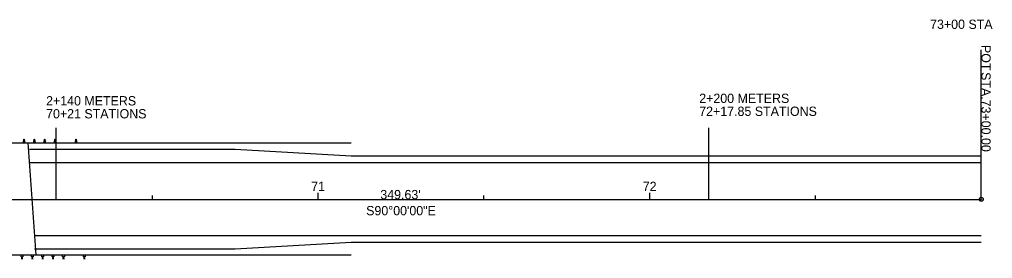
# Model space of a CAD drawing. Extents: x 27625 to 127752, y 6088 to 302357.
# Drawn here: x 27917.3 to 28210.8, y 6088.8 to 6160.8 of the extents above; entities that cross this region are included whole.
import ezdxf

# ---------------------------------------------------------------- set-up
doc = ezdxf.new("R2010")
doc.units = 0
for name, color, linetype in [('DR_X_Cells', 7, 'Continuous'), ('RS_Raster1', 7, 'Continuous'), ('RW_X_CL_100_Bearings', 7, 'Continuous'), ('RW_X_CL_100_Cardinal_Points', 7, 'Continuous'), ('RW_X_CL_100_Curve_Data', 7, 'Continuous'), ('RW_X_CL_100_Distances', 7, 'Continuous'), ('RW_X_CL_100_Stations', 7, 'Continuous'), ('SC_Scratch1', 7, 'Continuous'), ('SC_Scratch2', 7, 'Continuous'), ('SC_Scratch4', 7, 'Continuous'), ('SV_P_Control_Cells_Set', 7, 'Continuous'), ('SV_X_Mon_Cells_Found', 7, 'Continuous'), ('SV_X_Random_Point', 7, 'Continuous'), ('SV_X_Shot_Marker', 7, 'Continuous'), ('UT_X_Telecom_Cells', 7, 'Continuous')]:
    doc.layers.add(name, color=color, linetype=linetype)

msp = doc.modelspace()

# ---------------------------------------------------------------- linework, layer by layer
at = {"layer": 'DR_X_Cells'}
for p, q in [((27957.41, 6106.66), (27957.41, 6107.86)), ((28007.41, 6106.66), (28007.41, 6108.66)), ((28057.41, 6106.66), (28057.41, 6107.86)), ((28107.41, 6106.66), (28107.41, 6108.66)), ((28157.41, 6106.66), (28157.41, 6107.86))]:
    msp.add_line(p, q, dxfattribs=at)
at = {"layer": 'RS_Raster1'}
for centre in [(28007.41, 6106.66), (28107.41, 6106.66), (28207.41, 6106.66)]:
    msp.add_circle(centre, 0.05, dxfattribs=at)
at = {"layer": 'RW_X_CL_100_Bearings'}
for p, q in [((27904.89, 6123.66), (27919.89, 6123.66)), ((27919.89, 6123.66), (27922.25, 6089.91)), ((27907.25, 6089.91), (27922.25, 6089.91))]:
    msp.add_line(p, q, dxfattribs=at)
at = {"layer": 'RW_X_CL_100_Cardinal_Points'}
for p, q in [((27919.73, 6123.66), (27934.33, 6123.66)), ((27934.33, 6123.66), (27934.33, 6123.66)), ((27922.25, 6089.91), (27936.85, 6089.91)), ((27936.85, 6089.91), (27936.85, 6089.91))]:
    msp.add_line(p, q, dxfattribs=at)
at = {"layer": 'RW_X_CL_100_Curve_Data'}
for p, q in [((27918.45, 6124.72), (27918.96, 6124.72)), ((27918.45, 6124.72), (27918.45, 6124.68)), ((27918.45, 6124.68), (27918.66, 6124.68)), ((27918.45, 6124.23), (27918.45, 6124.19)), ((27918.45, 6124.23), (27918.66, 6124.23)), ((27918.45, 6124.19), (27918.96, 6124.19)), ((27918.45, 6124.19), (27918.45, 6123.66)), ((27918.69, 6124.65), (27918.69, 6124.26)), ((27918.72, 6124.65), (27918.72, 6124.26)), ((27918.75, 6124.68), (27918.96, 6124.68)), ((27918.75, 6124.23), (27918.96, 6124.23)), ((27918.96, 6124.72), (27918.96, 6124.68)), ((27918.96, 6124.23), (27918.96, 6124.19)), ((27918.96, 6123.66), (27918.96, 6124.19)), ((27921.58, 6124.72), (27922.09, 6124.72)), ((27921.58, 6124.72), (27921.58, 6124.68)), ((27921.58, 6124.68), (27921.78, 6124.68)), ((27921.58, 6124.23), (27921.58, 6124.19)), ((27921.58, 6124.23), (27921.78, 6124.23)), ((27921.58, 6124.19), (27922.09, 6124.19)), ((27921.58, 6124.19), (27921.58, 6123.66)), ((27921.81, 6124.65), (27921.81, 6124.26)), ((27921.85, 6124.65), (27921.85, 6124.26)), ((27921.88, 6124.68), (27922.09, 6124.68)), ((27921.88, 6124.23), (27922.09, 6124.23)), ((27922.09, 6124.72), (27922.09, 6124.68)), ((27922.09, 6124.23), (27922.09, 6124.19)), ((27922.09, 6123.66), (27922.09, 6124.19)), ((27924.7, 6124.72), (27925.21, 6124.72)), ((27924.7, 6124.72), (27924.7, 6124.68)), ((27924.7, 6124.68), (27924.91, 6124.68)), ((27924.7, 6124.23), (27924.7, 6124.19)), ((27924.7, 6124.23), (27924.91, 6124.23)), ((27924.7, 6124.19), (27925.21, 6124.19)), ((27924.7, 6124.19), (27924.7, 6123.66)), ((27924.94, 6124.65), (27924.94, 6124.26)), ((27924.97, 6124.65), (27924.97, 6124.26)), ((27925, 6124.68), (27925.21, 6124.68)), ((27925, 6124.23), (27925.21, 6124.23)), ((27925.21, 6124.72), (27925.21, 6124.68)), ((27925.21, 6124.23), (27925.21, 6124.19)), ((27925.21, 6123.66), (27925.21, 6124.19)), ((27927.83, 6124.72), (27928.34, 6124.72)), ((27927.83, 6124.72), (27927.83, 6124.68)), ((27927.83, 6124.68), (27928.03, 6124.68)), ((27927.83, 6124.23), (27927.83, 6124.19)), ((27927.83, 6124.23), (27928.03, 6124.23)), ((27927.83, 6124.19), (27928.34, 6124.19)), ((27927.83, 6124.19), (27927.83, 6123.66)), ((27928.06, 6124.65), (27928.06, 6124.26)), ((27928.1, 6124.65), (27928.1, 6124.26)), ((27928.13, 6124.68), (27928.34, 6124.68)), ((27928.13, 6124.23), (27928.34, 6124.23)), ((27928.34, 6124.72), (27928.34, 6124.68)), ((27928.34, 6124.23), (27928.34, 6124.19)), ((27928.34, 6123.66), (27928.34, 6124.19)), ((27934.08, 6124.72), (27934.59, 6124.72)), ((27934.08, 6124.72), (27934.08, 6124.68)), ((27934.08, 6124.68), (27934.28, 6124.68)), ((27934.08, 6124.23), (27934.08, 6124.19)), ((27934.08, 6124.23), (27934.28, 6124.23)), ((27934.08, 6124.19), (27934.59, 6124.19)), ((27934.08, 6124.19), (27934.08, 6123.66)), ((27934.31, 6124.65), (27934.31, 6124.26)), ((27934.35, 6124.65), (27934.35, 6124.26)), ((27934.38, 6124.68), (27934.59, 6124.68)), ((27934.38, 6124.23), (27934.59, 6124.23)), ((27934.59, 6124.72), (27934.59, 6124.68)), ((27934.59, 6124.23), (27934.59, 6124.19)), ((27934.59, 6123.66), (27934.59, 6124.19)), ((27917.85, 6089.38), (27917.85, 6089.91)), ((27917.85, 6089.38), (27918.36, 6089.38)), ((27917.85, 6089.34), (27917.85, 6089.38)), ((27917.85, 6089.34), (27918.05, 6089.34)), ((27917.85, 6088.85), (27917.85, 6088.88)), ((27917.85, 6088.88), (27918.05, 6088.88)), ((27917.85, 6088.85), (27918.36, 6088.85)), ((27918.08, 6088.91), (27918.08, 6089.31)), ((27918.12, 6088.91), (27918.12, 6089.31)), ((27918.15, 6089.34), (27918.36, 6089.34)), ((27918.15, 6088.88), (27918.36, 6088.88)), ((27918.36, 6089.91), (27918.36, 6089.38)), ((27918.36, 6089.34), (27918.36, 6089.38)), ((27918.36, 6088.85), (27918.36, 6088.88)), ((27920.97, 6089.38), (27920.97, 6089.91)), ((27920.97, 6089.38), (27921.48, 6089.38)), ((27920.97, 6089.34), (27920.97, 6089.38)), ((27920.97, 6089.34), (27921.18, 6089.34)), ((27920.97, 6088.85), (27920.97, 6088.88)), ((27920.97, 6088.88), (27921.18, 6088.88)), ((27920.97, 6088.85), (27921.48, 6088.85)), ((27921.21, 6088.91), (27921.21, 6089.31)), ((27921.24, 6088.91), (27921.24, 6089.31)), ((27921.27, 6089.34), (27921.48, 6089.34)), ((27921.27, 6088.88), (27921.48, 6088.88)), ((27921.48, 6089.91), (27921.48, 6089.38)), ((27921.48, 6089.34), (27921.48, 6089.38)), ((27921.48, 6088.85), (27921.48, 6088.88)), ((27924.1, 6089.38), (27924.1, 6089.91)), ((27924.1, 6089.38), (27924.61, 6089.38)), ((27924.1, 6089.34), (27924.1, 6089.38)), ((27924.1, 6089.34), (27924.3, 6089.34)), ((27924.1, 6088.85), (27924.1, 6088.88)), ((27924.1, 6088.88), (27924.3, 6088.88)), ((27924.1, 6088.85), (27924.61, 6088.85)), ((27924.33, 6088.91), (27924.33, 6089.31)), ((27924.37, 6088.91), (27924.37, 6089.31)), ((27924.4, 6089.34), (27924.61, 6089.34)), ((27924.4, 6088.88), (27924.61, 6088.88)), ((27924.61, 6089.91), (27924.61, 6089.38)), ((27924.61, 6089.34), (27924.61, 6089.38)), ((27924.61, 6088.85), (27924.61, 6088.88)), ((27927.22, 6089.38), (27927.22, 6089.91)), ((27927.22, 6089.38), (27927.73, 6089.38)), ((27927.22, 6089.34), (27927.22, 6089.38)), ((27927.22, 6089.34), (27927.43, 6089.34)), ((27927.22, 6088.85), (27927.22, 6088.88)), ((27927.22, 6088.88), (27927.43, 6088.88)), ((27927.22, 6088.85), (27927.73, 6088.85)), ((27927.46, 6088.91), (27927.46, 6089.31)), ((27927.49, 6088.91), (27927.49, 6089.31)), ((27927.52, 6089.34), (27927.73, 6089.34)), ((27927.52, 6088.88), (27927.73, 6088.88)), ((27927.73, 6089.91), (27927.73, 6089.38)), ((27927.73, 6089.34), (27927.73, 6089.38)), ((27927.73, 6088.85), (27927.73, 6088.88)), ((27930.35, 6089.38), (27930.35, 6089.91)), ((27930.35, 6089.38), (27930.86, 6089.38)), ((27930.35, 6089.34), (27930.35, 6089.38)), ((27930.35, 6089.34), (27930.55, 6089.34)), ((27930.35, 6088.85), (27930.35, 6088.88)), ((27930.35, 6088.88), (27930.55, 6088.88)), ((27930.35, 6088.85), (27930.86, 6088.85)), ((27930.58, 6088.91), (27930.58, 6089.31)), ((27930.62, 6088.91), (27930.62, 6089.31)), ((27930.65, 6089.34), (27930.86, 6089.34)), ((27930.65, 6088.88), (27930.86, 6088.88)), ((27930.86, 6089.91), (27930.86, 6089.38)), ((27930.86, 6089.34), (27930.86, 6089.38)), ((27930.86, 6088.85), (27930.86, 6088.88)), ((27936.6, 6089.38), (27936.6, 6089.91)), ((27936.6, 6089.38), (27937.11, 6089.38)), ((27936.6, 6089.34), (27936.6, 6089.38)), ((27936.6, 6089.34), (27936.8, 6089.34)), ((27936.6, 6088.85), (27936.6, 6088.88)), ((27936.6, 6088.88), (27936.8, 6088.88)), ((27936.6, 6088.85), (27937.11, 6088.85)), ((27936.83, 6088.91), (27936.83, 6089.31)), ((27936.87, 6088.91), (27936.87, 6089.31)), ((27936.9, 6089.34), (27937.11, 6089.34)), ((27936.9, 6088.88), (27937.11, 6088.88)), ((27937.11, 6089.91), (27937.11, 6089.38)), ((27937.11, 6089.34), (27937.11, 6089.38)), ((27937.11, 6088.85), (27937.11, 6088.88))]:
    msp.add_line(p, q, dxfattribs=at)
for centre, start, end in [((27918.66, 6124.65), 0, 90), ((27918.66, 6124.26), 270, 0), ((27918.75, 6124.65), 90, 180), ((27918.75, 6124.26), 180, 270), ((27921.78, 6124.65), 0, 90), ((27921.78, 6124.26), 270, 0), ((27921.88, 6124.65), 90, 180), ((27921.88, 6124.26), 180, 270), ((27924.91, 6124.65), 0, 90), ((27924.91, 6124.26), 270, 0), ((27925, 6124.65), 90, 180), ((27925, 6124.26), 180, 270), ((27928.03, 6124.65), 0, 90), ((27928.03, 6124.26), 270, 0), ((27928.13, 6124.65), 90, 180), ((27928.13, 6124.26), 180, 270), ((27934.28, 6124.65), 0, 90), ((27934.28, 6124.26), 270, 0), ((27934.38, 6124.65), 90, 180), ((27934.38, 6124.26), 180, 270), ((27918.05, 6089.31), 0, 90), ((27918.05, 6088.91), 270, 0), ((27918.15, 6089.31), 90, 180), ((27918.15, 6088.91), 180, 270), ((27921.18, 6089.31), 0, 90), ((27921.18, 6088.91), 270, 0), ((27921.27, 6089.31), 90, 180), ((27921.27, 6088.91), 180, 270), ((27924.3, 6089.31), 0, 90), ((27924.3, 6088.91), 270, 0), ((27924.4, 6089.31), 90, 180), ((27924.4, 6088.91), 180, 270), ((27927.43, 6089.31), 0, 90), ((27927.43, 6088.91), 270, 0), ((27927.52, 6089.31), 90, 180), ((27927.52, 6088.91), 180, 270), ((27930.55, 6089.31), 0, 90), ((27930.55, 6088.91), 270, 0), ((27930.65, 6089.31), 90, 180), ((27930.65, 6088.91), 180, 270), ((27936.8, 6089.31), 0, 90), ((27936.8, 6088.91), 270, 0), ((27936.9, 6089.31), 90, 180), ((27936.9, 6088.91), 180, 270)]:
    msp.add_arc(centre, 0.0312, start, end, dxfattribs=at)
at = {"layer": 'RW_X_CL_100_Distances'}
msp.add_line((27936.85, 6089.91), (28017.41, 6089.91), dxfattribs=at)
at = {"layer": 'RW_X_CL_100_Stations'}
for p, q in [((27918.45, 6123.66), (27918.96, 6123.66)), ((27921.58, 6123.66), (27922.09, 6123.66)), ((27924.7, 6123.66), (27925.21, 6123.66)), ((27927.83, 6123.66), (27928.34, 6123.66)), ((27934.08, 6123.66), (27934.59, 6123.66)), ((27917.85, 6089.91), (27918.36, 6089.91)), ((27920.97, 6089.91), (27921.48, 6089.91)), ((27924.1, 6089.91), (27924.61, 6089.91)), ((27927.22, 6089.91), (27927.73, 6089.91)), ((27930.35, 6089.91), (27930.86, 6089.91)), ((27936.6, 6089.91), (27937.11, 6089.91))]:
    msp.add_line(p, q, dxfattribs=at)
at = {"layer": 'SC_Scratch2'}
for p, q in [((27928.41, 6106.66), (27928.41, 6128.23)), ((28125.26, 6106.66), (28125.26, 6128.23)), ((28207.41, 6106.66), (28207.41, 6128.23))]:
    msp.add_line(p, q, dxfattribs=at)
at = {"layer": 'SV_P_Control_Cells_Set'}
msp.add_line((27934.33, 6123.66), (28017.41, 6123.66), dxfattribs=at)
at = {"layer": 'SV_X_Mon_Cells_Found'}
msp.add_line((28207.41, 6106.66), (28207.41, 6151.66), dxfattribs=at)
msp.add_circle((28207.41, 6106.66), 0.6, dxfattribs=at)
at = {"layer": 'SV_X_Random_Point'}
for p, q in [((27982.41, 6121.66), (27920.31, 6121.66)), ((28017.41, 6119.66), (27982.41, 6121.66)), ((28207.41, 6119.66), (28017.41, 6119.66)), ((28017.41, 6093.66), (27982.41, 6091.66)), ((28207.41, 6093.66), (28017.41, 6093.66)), ((27982.41, 6091.66), (27921.85, 6091.66))]:
    msp.add_line(p, q, dxfattribs=at)
at = {"layer": 'SV_X_Shot_Marker'}
msp.add_line((27857.78, 6106.66), (28207.41, 6106.66), dxfattribs=at)
at = {"layer": 'UT_X_Telecom_Cells'}
for p, q in [((28207.41, 6117.66), (27920.31, 6117.66)), ((28207.41, 6095.66), (27921.85, 6095.66))]:
    msp.add_line(p, q, dxfattribs=at)

# ---------------------------------------------------------------- texts
at = {"layer": 'DR_X_Cells'}
for s, p in [('71', (28005.3, 6109.16)), ('72', (28105.32, 6109.16))]:
    msp.add_text(s, height=2.8, rotation=360, dxfattribs=at).set_placement(p)
at = {"layer": 'SC_Scratch1'}
msp.add_text('S90°00\'00"E', height=2.8, rotation=360, dxfattribs=at).set_placement((28021.89, 6101.86))
at = {"layer": 'SC_Scratch2'}
for s, p in [('73+00 STA', (28191.99, 6157.97)), ('2+140 METERS', (27925.35, 6134.93)), ('2+200 METERS', (28122.35, 6135.68)), ('72+17.85 STATIONS', (28122.35, 6131.78)), ('70+21 STATIONS', (27925.35, 6131.03))]:
    msp.add_text(s, height=2.8, dxfattribs=at).set_placement(p)
at = {"layer": 'SC_Scratch4'}
msp.add_text("349.63'", height=2.8, rotation=360, dxfattribs=at).set_placement((28026.16, 6106.69))
at = {"layer": 'SV_X_Mon_Cells_Found'}
for s, p in [('POT', (28207.45, 6153.14)), (' STA. ', (28207.45, 6146.01)), ('73+00.00', (28207.45, 6136.69))]:
    msp.add_text(s, height=2.8, rotation=270, dxfattribs=at).set_placement(p)

doc.saveas('drawing.dxf')
